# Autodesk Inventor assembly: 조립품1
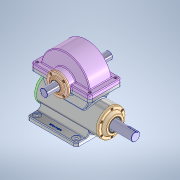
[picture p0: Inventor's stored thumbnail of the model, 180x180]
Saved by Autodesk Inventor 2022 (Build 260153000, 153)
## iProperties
Created: 2023-07
Part Number: 조립품1
Document SubType Name: Assembly
Designer: PC-13
Author: PC-13
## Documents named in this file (14)
- C:\Users\PC-13\Desktop\730706V1010\조립품1.iam
- C:\Users\PC-13\Desktop\730706V1010\부품1.ipt
- C:\Users\PC-13\Desktop\730706V1010\깊은 홈 볼 베어링 6209.ipt
- C:\Users\PC-13\Desktop\730706V1010\웜 샤프트.ipt
- C:\Users\PC-13\Desktop\730706V1010\뒤커버.ipt
- C:\Users\PC-13\Desktop\730706V1010\앞커버.ipt
- C:\Users\PC-13\Desktop\730706V1010\육각 소켓 머리 볼트 M5 x 12.ipt
- C:\Users\PC-13\Desktop\730706V1010\오일 실 35 55 11.ipt
- C:\Users\PC-13\Desktop\730706V1010\깊은 홈 볼 베어링 6206.ipt
- C:\Users\PC-13\Desktop\730706V1010\웜 휠.ipt
- C:\Users\PC-13\Desktop\730706V1010\본체 커버.ipt
- C:\Users\PC-13\Desktop\730706V1010\육각 소켓 머리 볼트 M6 x 20.ipt
- C:\Users\PC-13\Desktop\730706V1010\서브커버.ipt
- C:\Users\PC-13\Desktop\730706V1010\오일 실 30 42 7.ipt
